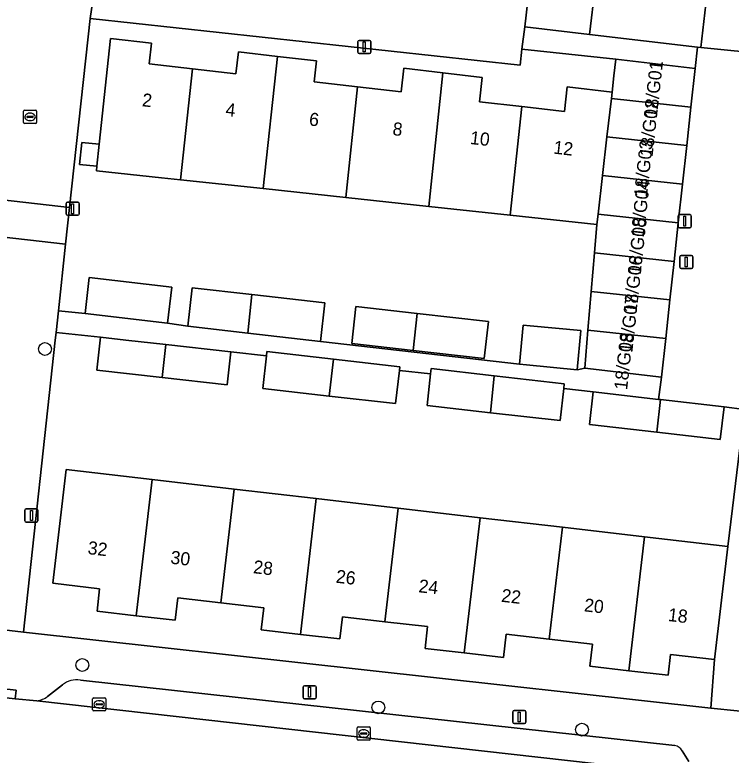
# Model space of a CAD drawing. Extents: x 162082 to 163401, y 388089 to 388636.
# Drawn here: x 162794 to 162848.7, y 388468.3 to 388524.8 of the extents above; entities that cross this region are included whole.
import ezdxf

# ---------------------------------------------------------------- set-up
doc = ezdxf.new("R2010")
doc.units = 0
for name, color, linetype in [('IMGEO_Boom', 7, 'Continuous'), ('IMGEO_Erf', 7, 'Continuous'), ('IMGEO_Kolk', 7, 'Continuous'), ('IMGEO_Lichtmast', 7, 'Continuous'), ('IMGEO_Muur', 7, 'Continuous'), ('IMGEO_Pand', 7, 'Continuous'), ('IMGEO_Pand_nummerreeks', 7, 'Continuous'), ('IMGEO_Parkeervlak_open', 7, 'Continuous'), ('IMGEO_Rijbaan_lokaal_open', 7, 'Continuous'), ('IMGEO_Voetpad_open', 7, 'Continuous')]:
    doc.layers.add(name, color=color, linetype=linetype)

msp = doc.modelspace()

# ---------------------------------------------------------------- linework, layer by layer
at = {"layer": 'IMGEO_Boom'}
for centre in [(162796.309, 388499.32), (162799.158, 388475.206), (162821.744, 388471.972), (162837.288, 388470.28)]:
    msp.add_circle(centre, 0.489, dxfattribs=at)
at = {"layer": 'IMGEO_Erf'}
for points in [[(162836.053, 388551.411), (162832.924, 388523.891), (162837.857, 388523.317), (162838.281, 388526.963)], [(162847.115, 388528.959), (162846.345, 388522.331), (162857.085, 388521.261), (162857.298, 388523.103), (162854.642, 388523.409), (162855.165, 388528.025)]]:
    msp.add_lwpolyline(points, dxfattribs=at)
for points in [[(162800.278, 388513.261), (162798.948, 388513.403), (162799.127, 388515.081), (162800.456, 388514.94), (162801.314, 388523.014), (162804.442, 388522.65), (162804.259, 388521.081), (162807.57, 388520.696), (162810.881, 388520.312), (162811.076, 388521.99), (162814.052, 388521.644), (162817.032, 388521.298), (162816.847, 388519.711), (162820.162, 388519.326), (162823.481, 388518.941), (162823.689, 388520.733), (162826.682, 388520.386), (162829.677, 388520.038), (162829.462, 388518.186), (162832.705, 388517.81), (162835.951, 388517.433), (162836.169, 388519.314), (162839.583, 388518.917), (162839.729, 388520.172), (162839.874, 388521.427), (162832.688, 388522.19), (162832.576, 388520.969), (162799.75, 388524.546), (162798.188, 388510.125), (162797.884, 388507.321), (162797.333, 388502.233), (162799.366, 388502.031), (162799.683, 388504.765), (162805.988, 388504.033), (162805.671, 388501.299), (162807.207, 388501.051), (162807.545, 388503.992), (162812.105, 388503.473), (162817.67, 388502.835), (162817.333, 388499.89), (162832.524, 388498.15), (162832.81, 388501.144), (162833.335, 388501.094), (162837.21, 388500.723), (162836.924, 388497.73), (162837.494, 388497.844), (162837.74, 388500.761), (162837.989, 388503.713), (162838.238, 388506.665), (162838.42, 388508.826), (162831.819, 388509.535), (162825.591, 388510.203), (162819.257, 388510.883), (162812.971, 388511.557), (162806.664, 388512.234), (162805.214, 388512.39), (162800.242, 388512.924)], [(162824.413, 388499.206), (162819.716, 388499.741), (162820.037, 388502.564), (162824.715, 388502.031), (162830.143, 388501.412), (162829.821, 388498.589)], [(162797.926, 388490.123), (162804.478, 388489.361), (162810.738, 388488.633), (162817.013, 388487.903), (162823.263, 388487.176), (162829.506, 388486.449), (162835.79, 388485.718), (162842.061, 388484.989), (162848.412, 388484.25), (162849.684, 388494.705), (162848.127, 388494.898), (162847.842, 388492.42), (162842.991, 388492.978), (162837.865, 388493.568), (162838.15, 388496.046), (162835.892, 388496.295), (162835.613, 388493.853), (162830.306, 388494.46), (162825.465, 388495.014), (162825.739, 388497.413), (162823.353, 388497.676), (162823.064, 388495.153), (162818.003, 388495.732), (162812.924, 388496.314), (162813.208, 388498.794), (162810.493, 388499.093), (162810.208, 388496.573), (162805.24, 388497.136), (162800.27, 388497.699), (162800.531, 388500), (162800.556, 388500.219), (162797.153, 388500.577), (162797.091, 388500), (162794.676, 388477.705), (162847.118, 388471.904), (162847.408, 388475.618), (162844.038, 388476.01), (162843.854, 388474.426), (162840.872, 388474.773), (162837.892, 388475.12), (162838.086, 388476.787), (162834.795, 388477.17), (162831.507, 388477.552), (162831.301, 388475.782), (162828.305, 388476.131), (162825.311, 388476.479), (162825.504, 388478.135), (162822.255, 388478.513), (162819.006, 388478.891), (162818.808, 388477.195), (162815.808, 388477.544), (162812.803, 388477.894), (162812.998, 388479.577), (162809.728, 388479.957), (162806.456, 388480.338), (162806.256, 388478.618), (162803.268, 388478.966), (162800.282, 388479.313), (162800.481, 388481.025), (162796.915, 388481.44)]]:
    msp.add_lwpolyline(points, close=True, dxfattribs=at)
at = {"layer": 'IMGEO_Kolk'}
for p, q in [((162794.673, 388516.604), (162794.673, 388517.456)), ((162794.748, 388517.53), (162795.6, 388517.53)), ((162795.161, 388517.31), (162795.186, 388517.31)), ((162795.674, 388517.456), (162795.674, 388516.604)), ((162794.932, 388517.024), (162794.932, 388517.036)), ((162795.37, 388516.987), (162794.972, 388516.987)), ((162794.975, 388517.073), (162795.373, 388517.073)), ((162795.184, 388516.75), (162795.159, 388516.75)), ((162795.416, 388517.036), (162795.416, 388517.024)), ((162795.6, 388516.53), (162794.748, 388516.53)), ((162799.949, 388471.78), (162799.949, 388472.632)), ((162800.024, 388472.706), (162800.876, 388472.706)), ((162800.437, 388472.486), (162800.462, 388472.486)), ((162800.95, 388472.632), (162800.95, 388471.78)), ((162800.208, 388472.2), (162800.208, 388472.212)), ((162800.646, 388472.163), (162800.248, 388472.163)), ((162800.251, 388472.249), (162800.649, 388472.249)), ((162800.46, 388471.926), (162800.435, 388471.926)), ((162800.692, 388472.212), (162800.692, 388472.2)), ((162800.876, 388471.706), (162800.024, 388471.706)), ((162820.135, 388469.555), (162820.135, 388470.407)), ((162820.21, 388470.481), (162821.062, 388470.481)), ((162820.623, 388470.261), (162820.648, 388470.261)), ((162821.136, 388470.407), (162821.136, 388469.555)), ((162820.394, 388469.975), (162820.394, 388469.987)), ((162820.832, 388469.938), (162820.434, 388469.938)), ((162820.437, 388470.024), (162820.835, 388470.024)), ((162820.646, 388469.701), (162820.621, 388469.701)), ((162820.878, 388469.987), (162820.878, 388469.975)), ((162821.062, 388469.481), (162820.21, 388469.481))]:
    msp.add_line(p, q, dxfattribs=at)
for points in [[(162794.673, 388516.604), (162794.673, 388517.456)], [(162794.748, 388517.53), (162795.6, 388517.53)], [(162795.674, 388517.456), (162795.674, 388516.604)], [(162795.6, 388516.53), (162794.748, 388516.53)], [(162799.949, 388471.78), (162799.949, 388472.632)], [(162800.024, 388472.706), (162800.876, 388472.706)], [(162800.95, 388472.632), (162800.95, 388471.78)], [(162800.876, 388471.706), (162800.024, 388471.706)], [(162820.135, 388469.555), (162820.135, 388470.407)], [(162820.21, 388470.481), (162821.062, 388470.481)], [(162821.136, 388470.407), (162821.136, 388469.555)], [(162821.062, 388469.481), (162820.21, 388469.481)]]:
    msp.add_lwpolyline(points, dxfattribs=at)
for centre, radius, start, end in [((162794.75, 388517.454), 0.0765, 91.552, 178.448), ((162794.75, 388517.454), 0.0765, 91.552, 178.448), ((162795.598, 388517.454), 0.0765, 1.552, 88.448), ((162795.598, 388517.454), 0.0765, 1.552, 88.448), ((162794.75, 388516.606), 0.0765, 181.552, 268.448), ((162794.75, 388516.606), 0.0765, 181.552, 268.448), ((162794.972, 388517.033), 0.0403, 85.8775, 175.7526), ((162794.969, 388517.023), 0.0366, 178.938, 274.7102), ((162795.373, 388517.03), 0.043, 264.8664, 352.4533), ((162795.377, 388517.035), 0.0386, 1.7309, 96.639), ((162795.598, 388516.606), 0.0765, 271.552, 358.448), ((162795.598, 388516.606), 0.0765, 271.552, 358.448), ((162800.026, 388472.63), 0.0765, 91.552, 178.448), ((162800.026, 388472.63), 0.0765, 91.552, 178.448), ((162800.874, 388472.63), 0.0765, 1.552, 88.448), ((162800.874, 388472.63), 0.0765, 1.552, 88.448), ((162800.248, 388472.209), 0.0403, 85.8775, 175.7526), ((162800.245, 388472.199), 0.0366, 178.938, 274.7102), ((162800.649, 388472.206), 0.043, 264.8664, 352.4533), ((162800.653, 388472.211), 0.0386, 1.7309, 96.639), ((162800.026, 388471.782), 0.0765, 181.552, 268.448), ((162800.026, 388471.782), 0.0765, 181.552, 268.448), ((162800.874, 388471.782), 0.0765, 271.552, 358.448), ((162800.874, 388471.782), 0.0765, 271.552, 358.448), ((162820.212, 388470.405), 0.0765, 91.552, 178.448), ((162820.212, 388470.405), 0.0765, 91.552, 178.448), ((162821.06, 388470.405), 0.0765, 1.552, 88.448), ((162821.06, 388470.405), 0.0765, 1.552, 88.448), ((162820.434, 388469.984), 0.0403, 85.8775, 175.7526), ((162820.431, 388469.974), 0.0366, 178.938, 274.7102), ((162820.835, 388469.981), 0.043, 264.8664, 352.4533), ((162820.839, 388469.986), 0.0386, 1.7309, 96.639), ((162820.212, 388469.557), 0.0765, 181.552, 268.448), ((162820.212, 388469.557), 0.0765, 181.552, 268.448), ((162821.06, 388469.557), 0.0765, 271.552, 358.448), ((162821.06, 388469.557), 0.0765, 271.552, 358.448)]:
    msp.add_arc(centre, radius, start, end, dxfattribs=at)
for centre, major_axis, ratio, start_param, end_param in [((162795.16, 388517.03), (-0.387, 0.002), 0.722429, 4.712389, 7.853982), ((162795.185, 388517.03), (-0.39, 0.002), 0.717154, 1.570796, 4.712389), ((162800.436, 388472.206), (-0.387, 0.002), 0.722429, 4.712389, 7.853982), ((162800.461, 388472.206), (-0.39, 0.002), 0.717154, 1.570796, 4.712389), ((162820.622, 388469.981), (-0.387, 0.002), 0.722429, 4.712389, 7.853982), ((162820.647, 388469.981), (-0.39, 0.002), 0.717154, 1.570796, 4.712389)]:
    msp.add_ellipse(centre, major_axis=major_axis, ratio=ratio, start_param=start_param, end_param=end_param, dxfattribs=at)
at = {"layer": 'IMGEO_Lichtmast'}
for p, q in [((162820.181, 388521.967), (162820.181, 388522.767)), ((162820.181, 388522.767), (162820.181, 388521.967)), ((162820.281, 388522.867), (162821.071, 388522.867)), ((162821.071, 388522.867), (162820.281, 388522.867)), ((162821.171, 388522.767), (162821.171, 388521.967)), ((162821.171, 388521.967), (162821.171, 388522.767)), ((162821.071, 388521.867), (162820.281, 388521.867)), ((162820.281, 388521.867), (162821.071, 388521.867)), ((162797.925, 388509.618), (162797.925, 388510.418)), ((162797.925, 388510.418), (162797.925, 388509.618)), ((162798.025, 388510.518), (162798.815, 388510.518)), ((162798.815, 388510.518), (162798.025, 388510.518)), ((162798.915, 388510.418), (162798.915, 388509.618)), ((162798.915, 388509.618), (162798.915, 388510.418)), ((162798.815, 388509.518), (162798.025, 388509.518)), ((162798.025, 388509.518), (162798.815, 388509.518)), ((162844.628, 388508.668), (162844.628, 388509.468)), ((162844.628, 388509.468), (162844.628, 388508.668)), ((162844.728, 388509.568), (162845.518, 388509.568)), ((162845.518, 388509.568), (162844.728, 388509.568)), ((162845.618, 388509.468), (162845.618, 388508.668)), ((162845.618, 388508.668), (162845.618, 388509.468)), ((162845.518, 388508.568), (162844.728, 388508.568)), ((162844.728, 388508.568), (162845.518, 388508.568)), ((162844.854, 388506.453), (162845.644, 388506.453)), ((162845.644, 388506.453), (162844.854, 388506.453)), ((162844.754, 388505.553), (162844.754, 388506.353)), ((162844.754, 388506.353), (162844.754, 388505.553)), ((162845.744, 388506.353), (162845.744, 388505.553)), ((162845.744, 388505.553), (162845.744, 388506.353)), ((162845.644, 388505.453), (162844.854, 388505.453)), ((162844.854, 388505.453), (162845.644, 388505.453)), ((162794.779, 388486.217), (162794.779, 388487.017)), ((162794.779, 388487.017), (162794.779, 388486.217)), ((162794.879, 388487.117), (162795.669, 388487.117)), ((162795.669, 388487.117), (162794.879, 388487.117)), ((162795.769, 388487.017), (162795.769, 388486.217)), ((162795.769, 388486.217), (162795.769, 388487.017)), ((162795.669, 388486.117), (162794.879, 388486.117)), ((162794.879, 388486.117), (162795.669, 388486.117)), ((162816.107, 388473.63), (162816.897, 388473.63)), ((162816.897, 388473.63), (162816.107, 388473.63)), ((162816.007, 388472.73), (162816.007, 388473.53)), ((162816.007, 388473.53), (162816.007, 388472.73)), ((162816.997, 388473.53), (162816.997, 388472.73)), ((162816.997, 388472.73), (162816.997, 388473.53)), ((162816.897, 388472.63), (162816.107, 388472.63)), ((162816.107, 388472.63), (162816.897, 388472.63)), ((162832.008, 388470.842), (162832.008, 388471.642)), ((162832.008, 388471.642), (162832.008, 388470.842)), ((162832.108, 388471.742), (162832.898, 388471.742)), ((162832.898, 388471.742), (162832.108, 388471.742)), ((162832.998, 388471.642), (162832.998, 388470.842)), ((162832.998, 388470.842), (162832.998, 388471.642)), ((162832.898, 388470.742), (162832.108, 388470.742)), ((162832.108, 388470.742), (162832.898, 388470.742))]:
    msp.add_line(p, q, dxfattribs=at)
for points in [[(162820.601, 388522.742), (162820.751, 388522.742), (162820.751, 388521.992), (162820.601, 388521.992), (162820.601, 388522.742)], [(162798.345, 388510.393), (162798.495, 388510.393), (162798.495, 388509.643), (162798.345, 388509.643), (162798.345, 388510.393)], [(162845.048, 388509.443), (162845.198, 388509.443), (162845.198, 388508.693), (162845.048, 388508.693), (162845.048, 388509.443)], [(162845.174, 388506.328), (162845.324, 388506.328), (162845.324, 388505.578), (162845.174, 388505.578), (162845.174, 388506.328)], [(162795.199, 388486.992), (162795.349, 388486.992), (162795.349, 388486.242), (162795.199, 388486.242), (162795.199, 388486.992)], [(162816.427, 388473.505), (162816.577, 388473.505), (162816.577, 388472.755), (162816.427, 388472.755), (162816.427, 388473.505)], [(162832.428, 388471.617), (162832.578, 388471.617), (162832.578, 388470.867), (162832.428, 388470.867), (162832.428, 388471.617)]]:
    msp.add_lwpolyline(points, dxfattribs=at)
for centre, start, end in [((162820.281, 388522.767), 90, 180), ((162820.281, 388522.767), 90, 180), ((162821.071, 388522.767), 0, 90), ((162821.071, 388522.767), 360, 90), ((162820.281, 388521.967), 180, 270), ((162820.281, 388521.967), 180, 270), ((162821.071, 388521.967), 270, 0), ((162821.071, 388521.967), 270, 0), ((162798.025, 388510.418), 90, 180), ((162798.025, 388510.418), 90, 180), ((162798.815, 388510.418), 0, 90), ((162798.815, 388510.418), 360, 90), ((162798.025, 388509.618), 180, 270), ((162798.025, 388509.618), 180, 270), ((162798.815, 388509.618), 270, 0), ((162798.815, 388509.618), 270, 0), ((162844.728, 388509.468), 90, 180), ((162844.728, 388509.468), 90, 180), ((162845.518, 388509.468), 0, 90), ((162845.518, 388509.468), 360, 90), ((162844.728, 388508.668), 180, 270), ((162844.728, 388508.668), 180, 270), ((162845.518, 388508.668), 270, 0), ((162845.518, 388508.668), 270, 0), ((162844.854, 388506.353), 90, 180), ((162844.854, 388506.353), 90, 180), ((162845.644, 388506.353), 0, 90), ((162845.644, 388506.353), 360, 90), ((162844.854, 388505.553), 180, 270), ((162844.854, 388505.553), 180, 270), ((162845.644, 388505.553), 270, 0), ((162845.644, 388505.553), 270, 0), ((162794.879, 388487.017), 90, 180), ((162794.879, 388487.017), 90, 180), ((162795.669, 388487.017), 0, 90), ((162795.669, 388487.017), 360, 90), ((162794.879, 388486.217), 180, 270), ((162794.879, 388486.217), 180, 270), ((162795.669, 388486.217), 270, 0), ((162795.669, 388486.217), 270, 0), ((162816.107, 388473.53), 90, 180), ((162816.107, 388473.53), 90, 180), ((162816.897, 388473.53), 0, 90), ((162816.897, 388473.53), 360, 90), ((162816.107, 388472.73), 180, 270), ((162816.107, 388472.73), 180, 270), ((162816.897, 388472.73), 270, 0), ((162816.897, 388472.73), 270, 0), ((162832.108, 388471.642), 90, 180), ((162832.108, 388471.642), 90, 180), ((162832.898, 388471.642), 0, 90), ((162832.898, 388471.642), 360, 90), ((162832.108, 388470.842), 180, 270), ((162832.108, 388470.842), 180, 270), ((162832.898, 388470.842), 270, 0), ((162832.898, 388470.842), 270, 0)]:
    msp.add_arc(centre, 0.1, start, end, dxfattribs=at)
at = {"layer": 'IMGEO_Muur'}
msp.add_lwpolyline([(162848.127, 388494.898), (162849.684, 388494.705), (162848.412, 388484.25)], dxfattribs=at)
at = {"layer": 'IMGEO_Pand'}
for points in [[(162836.941, 388530.14), (162836.594, 388527.159), (162838.281, 388526.963), (162837.857, 388523.317), (162846.104, 388522.359), (162846.345, 388522.331), (162847.115, 388528.959)], [(162807.57, 388520.696), (162804.259, 388521.081), (162804.442, 388522.65), (162801.314, 388523.014), (162800.456, 388514.94), (162800.278, 388513.261), (162800.242, 388512.924), (162805.214, 388512.39), (162806.664, 388512.234)], [(162812.971, 388511.557), (162814.052, 388521.644), (162811.076, 388521.99), (162810.881, 388520.312), (162807.57, 388520.696), (162806.664, 388512.234)], [(162819.257, 388510.883), (162820.162, 388519.326), (162816.847, 388519.711), (162817.032, 388521.298), (162814.052, 388521.644), (162812.971, 388511.557)], [(162839.583, 388518.917), (162839.528, 388518.442), (162845.598, 388517.781), (162845.919, 388520.725), (162839.874, 388521.427), (162839.729, 388520.172)], [(162819.257, 388510.883), (162825.591, 388510.203), (162826.682, 388520.386), (162823.689, 388520.733), (162823.481, 388518.941), (162820.162, 388519.326)], [(162832.705, 388517.81), (162829.462, 388518.186), (162829.677, 388520.038), (162826.682, 388520.386), (162825.591, 388510.203), (162831.819, 388509.535)], [(162838.511, 388509.615), (162838.85, 388512.557), (162839.189, 388515.499), (162839.528, 388518.442), (162839.583, 388518.917), (162836.169, 388519.314), (162835.951, 388517.433), (162832.705, 388517.81), (162831.819, 388509.535), (162838.42, 388508.826)], [(162839.189, 388515.499), (162845.278, 388514.836), (162845.598, 388517.781), (162839.528, 388518.442)], [(162838.85, 388512.557), (162844.957, 388511.892), (162845.278, 388514.836), (162839.189, 388515.499)], [(162800.456, 388514.94), (162799.127, 388515.081), (162798.948, 388513.403), (162800.278, 388513.261)], [(162838.511, 388509.615), (162844.636, 388508.948), (162844.957, 388511.892), (162838.85, 388512.557)], [(162838.511, 388509.615), (162838.42, 388508.826), (162838.238, 388506.665), (162844.315, 388506.003), (162844.636, 388508.948)], [(162837.989, 388503.713), (162843.994, 388503.059), (162844.315, 388506.003), (162838.238, 388506.665)], [(162805.671, 388501.299), (162805.988, 388504.033), (162799.683, 388504.765), (162799.366, 388502.031)], [(162812.105, 388503.473), (162807.545, 388503.992), (162807.207, 388501.051), (162811.789, 388500.525)], [(162843.674, 388500.114), (162843.994, 388503.059), (162837.989, 388503.713), (162837.74, 388500.761)], [(162812.105, 388503.473), (162811.789, 388500.525), (162817.333, 388499.89), (162817.67, 388502.835)], [(162824.715, 388502.031), (162820.037, 388502.564), (162819.716, 388499.741), (162824.413, 388499.206)], [(162824.715, 388502.031), (162824.413, 388499.206), (162829.821, 388498.589), (162830.143, 388501.412)], [(162837.21, 388500.723), (162833.335, 388501.094), (162832.81, 388501.144), (162832.524, 388498.15), (162833.049, 388498.1), (162836.924, 388497.73)], [(162843.674, 388500.114), (162837.74, 388500.761), (162837.494, 388497.844), (162843.353, 388497.17)], [(162805.24, 388497.136), (162805.525, 388499.656), (162802.489, 388500), (162800.556, 388500.219), (162800.531, 388500), (162800.27, 388497.699)], [(162805.24, 388497.136), (162810.208, 388496.573), (162810.493, 388499.093), (162805.525, 388499.656)], [(162818.325, 388498.545), (162813.246, 388499.126), (162813.208, 388498.794), (162812.924, 388496.314), (162818.003, 388495.732)], [(162823.353, 388497.676), (162823.386, 388497.965), (162818.325, 388498.545), (162818.003, 388495.732), (162823.064, 388495.153)], [(162830.588, 388497.27), (162825.786, 388497.82), (162825.739, 388497.413), (162825.465, 388495.014), (162830.306, 388494.46)], [(162835.892, 388496.295), (162835.934, 388496.658), (162830.588, 388497.27), (162830.306, 388494.46), (162835.613, 388493.853)], [(162842.991, 388492.978), (162843.279, 388495.456), (162843.137, 388495.472), (162838.15, 388496.046), (162837.865, 388493.568)], [(162842.991, 388492.978), (162847.842, 388492.42), (162848.127, 388494.898), (162843.279, 388495.456)], [(162803.268, 388478.966), (162804.478, 388489.361), (162797.926, 388490.123), (162796.915, 388481.44), (162800.481, 388481.025), (162800.282, 388479.313)], [(162803.268, 388478.966), (162806.256, 388478.618), (162806.456, 388480.338), (162809.728, 388479.957), (162810.738, 388488.633), (162804.478, 388489.361)], [(162817.013, 388487.903), (162810.738, 388488.633), (162809.728, 388479.957), (162812.998, 388479.577), (162812.803, 388477.894), (162815.808, 388477.544)], [(162817.013, 388487.903), (162815.808, 388477.544), (162818.808, 388477.195), (162819.006, 388478.891), (162822.255, 388478.513), (162823.263, 388487.176)], [(162828.305, 388476.131), (162829.506, 388486.449), (162823.263, 388487.176), (162822.255, 388478.513), (162825.504, 388478.135), (162825.311, 388476.479)], [(162828.305, 388476.131), (162831.301, 388475.782), (162831.507, 388477.552), (162834.795, 388477.17), (162835.79, 388485.718), (162829.506, 388486.449)], [(162840.872, 388474.773), (162842.061, 388484.989), (162835.79, 388485.718), (162834.795, 388477.17), (162838.086, 388476.787), (162837.892, 388475.12)], [(162840.872, 388474.773), (162843.854, 388474.426), (162844.038, 388476.01), (162847.408, 388475.618), (162848.412, 388484.25), (162842.061, 388484.989)]]:
    msp.add_lwpolyline(points, close=True, dxfattribs=at)
at = {"layer": 'IMGEO_Parkeervlak_open'}
for points in [[(162797.654, 388473.697), (162796.513, 388472.804)], [(162844.368, 388469.076), (162799.01, 388474.057)], [(162795.687, 388472.482), (162846.818, 388466.733)], [(162845.43, 388467.837), (162844.921, 388468.652)]]:
    msp.add_lwpolyline(points, dxfattribs=at)
for centre, radius, start, end in [((162798.738, 388472.349), 1.73, 80.944, 128.7925), ((162795.477, 388474.24), 1.77, 276.798, 305.7967), ((162844.195, 388468.278), 0.816, 27.2583, 77.7849)]:
    msp.add_arc(centre, radius, start, end, dxfattribs=at)
at = {"layer": 'IMGEO_Rijbaan_lokaal_open'}
for points in [[(162800.285, 388545.207), (162801.378, 388555.202), (162795.399, 388555.856), (162790.361, 388511.004), (162798.188, 388510.125), (162799.75, 388524.546), (162800.627, 388530.409), (162798.588, 388530.623)], [(162836.053, 388551.411), (162801.378, 388555.202), (162800.285, 388545.207), (162829.053, 388542.324), (162827.637, 388527.57), (162821.57, 388528.208), (162819.581, 388528.417), (162802.616, 388530.2), (162800.627, 388530.409), (162799.75, 388524.546), (162832.576, 388520.969), (162832.688, 388522.19), (162832.924, 388523.891)], [(162837.857, 388523.317), (162832.924, 388523.891), (162832.688, 388522.19), (162839.874, 388521.427), (162845.919, 388520.725), (162846.104, 388522.359)], [(162797.884, 388507.321), (162798.188, 388510.125), (162790.361, 388511.004), (162790.046, 388508.201)], [(162797.091, 388500), (162797.153, 388500.577), (162797.333, 388502.233), (162797.884, 388507.321), (162790.046, 388508.201), (162789.54, 388503.424), (162789.374, 388501.858), (162789.139, 388499.763), (162786.727, 388478.655), (162794.676, 388477.705)]]:
    msp.add_lwpolyline(points, close=True, dxfattribs=at)
for points in [[(162857.085, 388521.261), (162846.345, 388522.331), (162846.104, 388522.359), (162845.919, 388520.725), (162845.598, 388517.781), (162845.278, 388514.836), (162844.957, 388511.892), (162844.636, 388508.948), (162844.315, 388506.003), (162843.994, 388503.059), (162843.674, 388500.114), (162843.353, 388497.17), (162843.137, 388495.472), (162843.279, 388495.456), (162848.127, 388494.898), (162849.684, 388494.705), (162848.412, 388484.25), (162847.408, 388475.618), (162847.118, 388471.904), (162853.139, 388471.305)], [(162884.626, 388462.489), (162876.83, 388463.357), (162855.559, 388465.713), (162851.737, 388466.136), (162847.428, 388466.664), (162846.818, 388466.733), (162795.687, 388472.482), (162794.041, 388472.628), (162786.019, 388473.51), (162784.746, 388473.713), (162740.592, 388478.592), (162739.134, 388478.857), (162738.428, 388472.787), (162742.707, 388472.238), (162757.624, 388470.527), (162759.881, 388470.341), (162827.517, 388462.78), (162833.436, 388462.073), (162853.043, 388459.912), (162856.186, 388459.572), (162858.177, 388459.371), (162896.45, 388455.19)]]:
    msp.add_lwpolyline(points, dxfattribs=at)
at = {"layer": 'IMGEO_Voetpad_open'}
for points in [[(162817.333, 388499.89), (162811.789, 388500.525), (162807.207, 388501.051), (162805.671, 388501.299), (162799.366, 388502.031), (162797.333, 388502.233), (162797.153, 388500.577), (162800.556, 388500.219), (162802.489, 388500), (162805.525, 388499.656), (162810.493, 388499.093), (162813.208, 388498.794), (162813.246, 388499.126), (162818.325, 388498.545), (162823.386, 388497.965), (162823.353, 388497.676), (162825.739, 388497.413), (162825.786, 388497.82), (162830.588, 388497.27), (162835.934, 388496.658), (162835.892, 388496.295), (162838.15, 388496.046), (162843.137, 388495.472), (162843.353, 388497.17), (162837.494, 388497.844), (162836.924, 388497.73), (162833.049, 388498.1), (162832.524, 388498.15)], [(162786.091, 388474.165), (162786.019, 388473.51), (162794.041, 388472.628), (162794.113, 388473.277)]]:
    msp.add_lwpolyline(points, close=True, dxfattribs=at)
for points in [[(162877.252, 388468.541), (162871.805, 388469.165), (162856.628, 388470.904), (162853.139, 388471.305), (162847.118, 388471.904), (162794.676, 388477.705), (162786.727, 388478.655), (162739.055, 388483.959)], [(162784.746, 388473.713), (162786.019, 388473.51), (162786.091, 388474.165), (162794.113, 388473.277), (162794.041, 388472.628), (162795.687, 388472.482)], [(162796.513, 388472.804), (162797.654, 388473.697)], [(162799.01, 388474.057), (162844.368, 388469.076)], [(162844.921, 388468.652), (162845.43, 388467.837)]]:
    msp.add_lwpolyline(points, dxfattribs=at)
for centre, radius, start, end in [((162798.738, 388472.349), 1.73, 80.944, 128.7925), ((162795.477, 388474.24), 1.77, 276.798, 305.7967), ((162844.195, 388468.278), 0.816, 27.2583, 77.7849)]:
    msp.add_arc(centre, radius, start, end, dxfattribs=at)

# ---------------------------------------------------------------- texts
at = {"layer": 'IMGEO_Pand_nummerreeks'}
for s, rotation, p in [('18/G01', 83.7061, (162842.996, 388516.898)), ('2', 353.4224, (162803.682, 388517.848)), ('18/G02', 83.7061, (162842.671, 388513.949)), ('4', 353.4243, (162810.053, 388517.114)), ('6', 353.4243, (162816.423, 388516.38)), ('8', 353.4243, (162822.796, 388515.644)), ('10', 353.4243, (162828.71, 388514.964)), ('12', 353.4243, (162835.074, 388514.23)), ('18/G03', 83.7061, (162842.234, 388510.849)), ('18/G04', 83.7061, (162841.996, 388507.799)), ('18/G05', 83.7061, (162841.759, 388504.948)), ('18/G06', 83.7061, (162841.442, 388502.017)), ('18/G07', 83.7061, (162841.125, 388499.007)), ('18/G08', 83.7061, (162840.729, 388496.159)), ('32', 353.4227, (162799.536, 388483.675)), ('30', 353.4227, (162805.854, 388482.946)), ('28', 353.4227, (162812.165, 388482.219)), ('26', 353.4227, (162818.474, 388481.491)), ('24', 353.4227, (162824.785, 388480.763)), ('22', 353.4227, (162831.094, 388480.036)), ('20', 353.4227, (162837.412, 388479.308)), ('18', 353.4227, (162843.813, 388478.57))]:
    msp.add_text(s, height=1, rotation=rotation, dxfattribs=at).set_placement(p)

doc.saveas('drawing.dxf')
